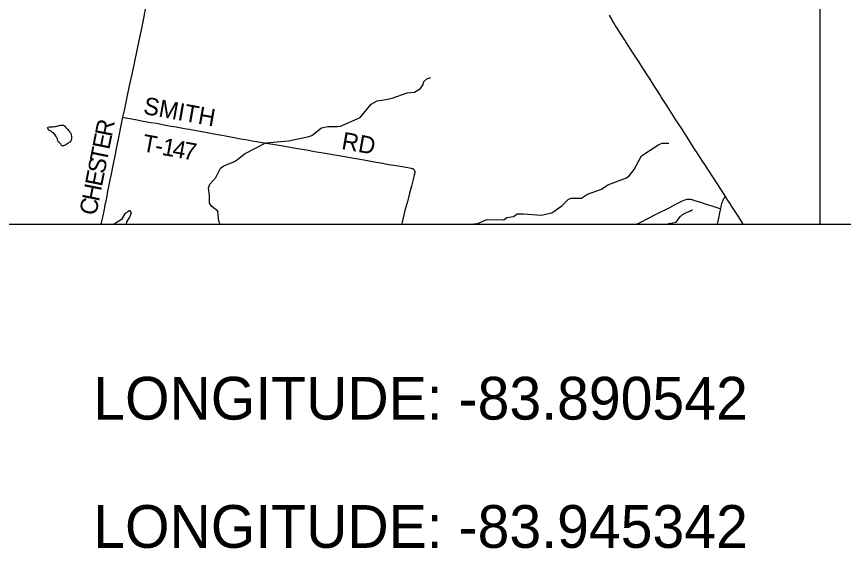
# Model space of a CAD drawing. Extents: x -1.4 to 35.4, y 0 to 22.
# Drawn here: x 13.799 to 16.506, y 11.993 to 13.734 of the extents above; entities that cross this region are included whole.
import ezdxf

# ---------------------------------------------------------------- set-up
doc = ezdxf.new("R2010")
doc.units = 0
for name, color, linetype in [('GM_X_County_Road', 7, 'Continuous'), ('GM_X_County_Road_Text', 7, 'Continuous'), ('GM_X_Minor_Lake', 7, 'Continuous'), ('GM_X_Minor_River', 7, 'Continuous'), ('GM_X_Township_Road', 7, 'Continuous'), ('GM_X_Township_Road_Text', 7, 'Continuous'), ('GM_X_US_Route', 7, 'Continuous'), ('SC_Scratch1', 7, 'Continuous'), ('SH_Border', 7, 'Continuous'), ('SH_Text', 7, 'Continuous')]:
    doc.layers.add(name, color=color, linetype=linetype)

msp = doc.modelspace()

# ---------------------------------------------------------------- linework, layer by layer
at = {"layer": 'GM_X_County_Road'}
for points in [[(14.1471, 13.4045), (14.1519, 13.4269), (14.1622, 13.4757), (14.169, 13.5079), (14.1771, 13.5456), (14.1836, 13.576), (14.186, 13.5875), (14.1992, 13.6508), (14.2084, 13.6952), (14.2143, 13.7238), (14.2214, 13.7578), (14.2316, 13.8071), (14.2377, 13.8363), (14.2449, 13.871), (14.2568, 13.9282), (14.2649, 13.9658), (14.2706, 13.9929), (14.2769, 14.0188), (14.2807, 14.033), (14.283, 14.0418), (14.2865, 14.0548)], [(14.0762, 13.0546), (14.0783, 13.0645), (14.0809, 13.077), (14.0831, 13.0885), (14.084, 13.0927), (14.0851, 13.0981), (14.0862, 13.1029), (14.0893, 13.1187), (14.0916, 13.1303), (14.0949, 13.1467), (14.0981, 13.1625), (14.1002, 13.1728), (14.1057, 13.2002), (14.1094, 13.2179), (14.113, 13.2355), (14.1151, 13.2465), (14.1228, 13.2842), (14.1276, 13.3073), (14.1328, 13.3334), (14.1425, 13.3834), (14.1471, 13.4045)]]:
    msp.add_lwpolyline(points, dxfattribs=at)
at = {"layer": 'GM_X_Minor_Lake'}
for points in [[(13.8997, 13.3702), (13.9001, 13.3705), (13.9016, 13.3721), (13.9065, 13.3732), (13.9119, 13.3735), (13.9176, 13.3738), (13.9221, 13.3742), (13.9267, 13.3749), (13.9305, 13.3757), (13.9339, 13.3764), (13.9374, 13.3775), (13.94, 13.3782), (13.9423, 13.3786), (13.9446, 13.379), (13.9476, 13.3793), (13.9503, 13.3793), (13.9522, 13.3793), (13.9552, 13.3762), (13.959, 13.3724), (13.9632, 13.3674), (13.9669, 13.3644), (13.9692, 13.3617), (13.9711, 13.3586), (13.973, 13.356), (13.9748, 13.3537), (13.976, 13.351), (13.9771, 13.3487), (13.9786, 13.3422), (13.9785, 13.3377), (13.9789, 13.3358), (13.9781, 13.3327), (13.9777, 13.3308), (13.9773, 13.3282), (13.9754, 13.3259), (13.9739, 13.3236), (13.9712, 13.3218), (13.9685, 13.3206), (13.9662, 13.3184), (13.9628, 13.3161), (13.9582, 13.3135), (13.9521, 13.3116), (13.9491, 13.3109), (13.9468, 13.3102), (13.9434, 13.3163), (13.9378, 13.3216), (13.9351, 13.3243), (13.934, 13.3285), (13.9325, 13.3327), (13.9314, 13.3357), (13.9306, 13.3376), (13.9284, 13.3418), (13.9261, 13.3453), (13.9242, 13.3479), (13.922, 13.3502), (13.9193, 13.3533), (13.9174, 13.3541), (13.914, 13.3571), (13.911, 13.3594), (13.9084, 13.3606), (13.9065, 13.3618), (13.9046, 13.3629), (13.8997, 13.3702)], [(14.1584, 13.0546), (14.16, 13.0617), (14.1695, 13.0778), (14.1747, 13.0932), (14.1692, 13.0991), (14.1538, 13.0884), (14.142, 13.0697), (14.1251, 13.0587), (14.1173, 13.0546)]]:
    msp.add_lwpolyline(points, dxfattribs=at)
at = {"layer": 'GM_X_Minor_River'}
for points in [[(14.465, 13.0546), (14.4614, 13.0638), (14.4579, 13.0976), (14.4377, 13.1122), (14.4307, 13.123), (14.4309, 13.1484), (14.4269, 13.1728), (14.4313, 13.1856), (14.4508, 13.2072), (14.4662, 13.2376), (14.477, 13.2454), (14.5122, 13.2597), (14.5218, 13.2663), (14.545, 13.2852), (14.6148, 13.3211), (14.689, 13.3278), (14.7557, 13.3414), (14.7652, 13.3454), (14.7969, 13.3701), (14.8178, 13.3741), (14.8501, 13.3745), (14.86, 13.3751), (14.9244, 13.4039), (14.9602, 13.4476), (14.9798, 13.4589), (15.0022, 13.4618), (15.0282, 13.4672), (15.0775, 13.4847), (15.1014, 13.4864), (15.1218, 13.4992), (15.13, 13.5116), (15.1321, 13.5214), (15.1426, 13.5307), (15.1556, 13.5349)], [(15.2856, 13.0546), (15.2956, 13.0557), (15.3055, 13.0554), (15.3391, 13.0695), (15.3942, 13.0689), (15.4038, 13.0767), (15.4255, 13.08), (15.4378, 13.0888), (15.4583, 13.0883), (15.517, 13.0835), (15.5514, 13.0922), (15.5841, 13.1143), (15.6058, 13.1369), (15.6161, 13.1401), (15.6271, 13.1395), (15.6381, 13.1396), (15.6491, 13.1401), (15.6688, 13.1533), (15.7147, 13.1693), (15.7351, 13.1829), (15.7963, 13.2065), (15.8059, 13.2139), (15.8215, 13.2337), (15.8456, 13.2779), (15.9018, 13.315), (15.9133, 13.3193), (15.9349, 13.3203)], [(15.959, 13.0609), (15.973, 13.0803), (15.9749, 13.0821), (15.9772, 13.084), (15.9795, 13.0858), (15.9822, 13.0877), (15.9845, 13.0892), (15.9879, 13.091), (15.9906, 13.0917), (15.9948, 13.0939), (15.9975, 13.0954), (16.0006, 13.0965), (16.0025, 13.0972), (16.0044, 13.0979), (16.0063, 13.0986), (16.0082, 13.0998), (16.0109, 13.1012), (16.0117, 13.1012), (16.012, 13.1012)], [(15.9307, 13.0546), (15.9342, 13.0571), (15.959, 13.0609)]]:
    msp.add_lwpolyline(points, dxfattribs=at)
at = {"layer": 'GM_X_Township_Road'}
for points in [[(14.1471, 13.4045), (14.1499, 13.404), (14.1569, 13.4026), (14.1698, 13.4003), (14.1881, 13.397), (14.2138, 13.3924), (14.2382, 13.388), (14.2566, 13.3848), (14.2823, 13.3801), (14.3044, 13.376), (14.3214, 13.3729), (14.3428, 13.3691), (14.3554, 13.3669), (14.3644, 13.3652), (14.3874, 13.3611), (14.4228, 13.3547), (14.4448, 13.3505), (14.4711, 13.3457), (14.4827, 13.3436), (14.5003, 13.3406), (14.5167, 13.3375), (14.5321, 13.3345), (14.5485, 13.3315), (14.5601, 13.3295), (14.5705, 13.3277), (14.5849, 13.3252), (14.6018, 13.3222), (14.6237, 13.3182), (14.672, 13.3106), (14.6996, 13.3058), (14.7267, 13.3011), (14.7479, 13.2975), (14.7743, 13.293), (14.8022, 13.2883), (14.8471, 13.2805), (14.9046, 13.2706), (14.9358, 13.2652), (14.9759, 13.258), (14.9913, 13.2551), (15.0175, 13.2505), (15.0423, 13.2463), (15.0675, 13.2419), (15.0859, 13.2388), (15.0914, 13.2379), (15.0945, 13.2371), (15.096, 13.2364), (15.0972, 13.2357), (15.0983, 13.2349), (15.0992, 13.2342), (15.1004, 13.2328), (15.1011, 13.2317), (15.1017, 13.2307), (15.1021, 13.2296), (15.1025, 13.2285), (15.1027, 13.2272), (15.1029, 13.2255), (15.1028, 13.2239), (15.1025, 13.2222), (15.1011, 13.2162), (15.0973, 13.2011), (15.0917, 13.1792), (15.0858, 13.156), (15.0812, 13.1379), (15.0787, 13.1289), (15.0736, 13.1104), (15.0706, 13.0997), (15.068, 13.0894), (15.0613, 13.0607), (15.0598, 13.0546)], [(15.8291, 13.0546), (15.8404, 13.0603), (15.8932, 13.0868), (15.9376, 13.1092), (15.9558, 13.1186), (15.9712, 13.1267), (15.9795, 13.1309), (15.9847, 13.1331), (15.9899, 13.1349), (15.9942, 13.136), (15.998, 13.1365), (16.0016, 13.1368), (16.0035, 13.1367), (16.0055, 13.1364), (16.0084, 13.1357), (16.0108, 13.1351), (16.0137, 13.1342), (16.0192, 13.1324), (16.038, 13.1263), (16.0597, 13.1193), (16.0751, 13.1146), (16.0988, 13.1075), (16.1048, 13.1056)], [(16.1048, 13.1056), (16.1056, 13.1099), (16.1065, 13.114), (16.1075, 13.118), (16.1086, 13.1223), (16.1094, 13.1252), (16.1103, 13.1281), (16.1112, 13.1307), (16.1122, 13.1333), (16.1135, 13.1359), (16.1149, 13.1382), (16.1165, 13.1405), (16.1178, 13.142), (16.1202, 13.1449)], [(16.0943, 13.0546), (16.0985, 13.0747), (16.1021, 13.0921), (16.1041, 13.1018), (16.1048, 13.1056)]]:
    msp.add_lwpolyline(points, dxfattribs=at)
at = {"layer": 'GM_X_US_Route'}
msp.add_lwpolyline([(16.1786, 13.0546), (16.1629, 13.0794), (16.1524, 13.0956), (16.1391, 13.1158), (16.134, 13.1236), (16.1249, 13.1377), (16.1202, 13.1449), (16.1164, 13.1507), (16.0804, 13.2066), (16.062, 13.2346), (16.0499, 13.2534), (16.0465, 13.2586), (16.0398, 13.2691), (16.0272, 13.2883), (16.0177, 13.3029), (15.9942, 13.3395), (15.9734, 13.3719), (15.968, 13.3803), (15.9623, 13.3892), (15.9556, 13.3996), (15.9335, 13.4341), (15.9255, 13.4467), (15.9108, 13.4698), (15.9048, 13.4792), (15.8972, 13.4913), (15.8864, 13.508), (15.8708, 13.5327), (15.8658, 13.5405), (15.8516, 13.5625), (15.8371, 13.5849), (15.8203, 13.611), (15.8034, 13.6369), (15.7943, 13.6512), (15.7913, 13.6559), (15.7886, 13.6601), (15.7782, 13.6762), (15.7765, 13.6788), (15.7729, 13.6846), (15.7652, 13.6966), (15.7603, 13.7045), (15.7548, 13.7135), (15.7507, 13.7204), (15.7476, 13.7258), (15.7402, 13.7387)], dxfattribs=at)
at = {"layer": 'SC_Scratch1'}
msp.add_line((-1.4282, 13.0546), (35.3749, 13.0546), dxfattribs=at)
msp.add_lwpolyline([(13.5799, 13.0546), (16.4299, 13.0546), (16.4299, 15.2626)], dxfattribs=at)
at = {"layer": 'SH_Border'}
msp.add_lwpolyline([(9.6299, 19.8546), (9.6299, 13.0546), (16.4299, 13.0546), (16.4299, 19.8546)], close=True, dxfattribs=at)

# ---------------------------------------------------------------- texts
at = {"layer": 'GM_X_County_Road_Text'}
for s, rotation, p in [('R', 78.6901, (14.1105, 13.3382)), ('E', 78.7556, (14.1022, 13.2965)), ('T', 78.7556, (14.0939, 13.2548)), ('S', 78.7548, (14.0865, 13.2172)), ('E', 78.7556, (14.0782, 13.1755)), ('H', 78.7594, (14.0684, 13.1265)), ('C', 78.7583, (14.0593, 13.0807))]:
    msp.add_text(s, height=0.0568, rotation=rotation, dxfattribs=at).set_placement(p)
at = {"layer": 'GM_X_Township_Road_Text'}
for s, height, rotation, p in [('SMITH', 0.05682, 349.8511, (14.2114, 13.4161)), ('RD', 0.05682, 350.0473, (14.8604, 13.3011)), ('T', 0.0568, 349.497, (14.2072, 13.2939)), ('1', 0.0568, 349.5223, (14.2719, 13.2819)), ('4', 0.0568, 349.6238, (14.3064, 13.2756)), ('7', 0.0568, 349.9745, (14.3412, 13.2692)), ('-', 0.0568, 349.5115, (14.249, 13.2862))]:
    msp.add_text(s, height=height, rotation=rotation, dxfattribs=at).set_placement(p)
at = {"layer": 'SH_Text'}
for s, p in [('LONGITUDE: -83.890542', (14.0499, 12.4146)), ('LONGITUDE: -83.945342', (14.0499, 11.9946))]:
    msp.add_text(s, height=0.14, dxfattribs=at).set_placement(p)

doc.saveas('drawing.dxf')
